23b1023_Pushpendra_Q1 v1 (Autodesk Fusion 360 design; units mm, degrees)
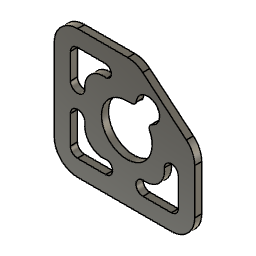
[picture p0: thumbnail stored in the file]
sketch "Sketch1" plane through (0, 0, 0) normal (0, 1, 0) x axis (1, 0, 0)
  line L1 (20, -15) -> (-20, -15)
  line L2 (-30, -60) -> (-30, -25)
  line L3 (30, -25) -> (30, -44.3594)
  line L4 (26.4279, -52.0199) -> (7.7882, -67.6604)
  line L5 (1.3603, -70) -> (-20, -70)
  line L6 (22.9999, -24.9094) -> (22.9999, -37.0105)
  line L7 (7.8783, -21.9094) -> (19.9999, -21.9094)
  line L8 (-8, -22) -> (-20.1275, -22)
  line L9 (-23.1275, -37) -> (-23.1275, -25)
  line L10 (-23.0938, -49.0756) -> (-23.0938, -60.0188)
  line L11 (-8.2151, -63.0188) -> (-20.0938, -63.0188)
  line L12 (2.904, -53.8167) -> (1, -53.8167)
  arc A1 centre (-20, -25) radius 10 clockwise from (-30, -25) to (-20, -15)
  arc A2 centre (20, -25) radius 10 clockwise from (20, -15) to (30, -25)
  arc A3 centre (20, -44.3594) radius 10 clockwise from (30, -44.3594) to (26.4279, -52.0199)
  arc A4 centre (1.3603, -60) radius 10 clockwise from (7.7882, -67.6604) to (1.3603, -70)
  arc A5 centre (19.9999, -24.9094) radius 3 clockwise from (19.9999, -21.9094) to (22.9999, -24.9094)
  arc A6 centre (19.9999, -37.0105) radius 3 clockwise from (22.9999, -37.0105) to (16.9999, -37.0014)
  arc A7 centre (7.8783, -24.9111) radius 3.0017 clockwise from (7.9983, -27.9104) to (7.8783, -21.9094)
  arc A8 centre (9.0852, -35.8363) radius 8 clockwise from (7.9983, -27.9104) to (16.9999, -37.0014)
  arc A9 centre (-20, -60) radius 10 clockwise from (-20, -70) to (-30, -60)
  arc A10 centre (-20.1275, -25) radius 3 clockwise from (-23.1275, -25) to (-20.1275, -22)
  arc A11 centre (-19.9988, -37) radius 3.1287 clockwise from (-16.8978, -36.5849) to (-23.1275, -37)
  arc A12 centre (-8, -24.927) radius 2.927 clockwise from (-8, -22) to (-7.1595, -27.7307)
  arc A13 centre (-8.9686, -35.5235) radius 8 clockwise from (-16.8978, -36.5849) to (-7.1595, -27.7307)
  arc A14 centre (-20.0938, -60.0188) radius 3 clockwise from (-20.0938, -63.0188) to (-23.0938, -60.0188)
  arc A15 centre (-20.0195, -49.0756) radius 3.0743 clockwise from (-23.0938, -49.0756) to (-16.9559, -49.3312)
  arc A16 centre (-8.2151, -60.4004) radius 2.6184 clockwise from (-7.5526, -57.8672) to (-8.2151, -63.0188)
  arc A17 centre (-8.9836, -49.9962) radius 8 clockwise from (-7.5526, -57.8672) to (-16.9559, -49.3312)
  arc A18 centre (1, -43) radius 10.8167 clockwise from (1, -53.8167) to (10.6868, -47.813)
  arc A19 centre (10, -55) radius 5 clockwise from (10.6868, -50.0474) to (5.0079, -55.2801)
  arc A20 centre (2.904, -56.0607) radius 2.244 clockwise from (2.904, -53.8167) to (5.0079, -55.2801)
  arc A21 centre (12.3177, -48.6233) radius 1.8211 clockwise from (11.9965, -50.4159) to (10.6868, -47.813)
  point P2 (30, -15)
  point P3 (-30, -70)
  point P54 (11.9965, -50.4159)
  point P53 (5.0079, -55.2801)
  point P55 (5.0079, -55.2801)
  point P59 (11.9965, -50.4159)
  point P4 (-30, -25)
  point P5 (-20, -15)
  horizontal L1
  perpendicular L1 L2
  tangent L2 A1
  tangent L1 A1
  perpendicular L1 L3
  coincident P2 L1
  coincident P2 L3
  tangent L1 A2
  tangent L3 A2
  tangent L3 A3
  tangent L4 A3
  perpendicular L2 L5
  tangent L5 A4
  tangent L4 A4
  vertical L6
  perpendicular L2 L7
  tangent L6 A5
  tangent L7 A5
  tangent L6 A6
  tangent L7 A7
  coincident P3 L5
  coincident P3 L2
  tangent L5 A9
  tangent L2 A9
  horizontal L8
  vertical L9
  tangent L8 A10
  tangent L9 A10
  tangent L9 A11
  tangent L8 A12
  tangent A11 A13
  vertical L10
  perpendicular L10 L11
  tangent L10 A14
  tangent L11 A14
  tangent L10 A15
  tangent L11 A16
  tangent A15 A17
  tangent A18 L12
  parallel L5 L12
  coincident A19 P54
  coincident P53 P55
  tangent L12 A20
  coincident P54 P59
  tangent A18 A21
  dimension "d1" radius A1 = 10
  dimension "d2" distance P3 P4 = 45
  dimension "d3" distance P2 P5 = 50
  dimension "d4" angle L3 L4 = 130
  dimension "d5" radius A2 = 10
  dimension "d6" radius A3 = 10
  dimension "d7" radius A4 = 10
  dimension "d8" radius A5 = 3
  dimension "d9" radius A8 = 8
  dimension "d10" radius A9 = 10
  dimension "d11" radius A10 = 3
  dimension "d12" radius A13 = 8
  dimension "d13" radius A14 = 3
  dimension "d14" radius A17 = 8
  dimension "d15" diameter A18 = 21.6333
  dimension "d16" diameter A19 = 10
extrude "Extrude1" new body sketch "Sketch1" along normal blind 3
